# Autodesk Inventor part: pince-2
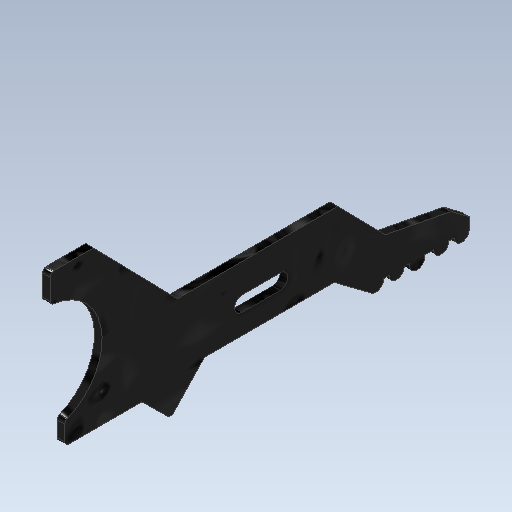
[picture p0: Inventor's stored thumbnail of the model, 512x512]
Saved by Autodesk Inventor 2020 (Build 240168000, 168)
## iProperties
Created: 2021-10
Part Number: pince-2
Material: Générique
Document SubType Name: Modeling
Designer: bruno
Density: 1 g/cm^3
Appearance: Noir
Mass: 0.477223 g
Surface Area: 11.2453 cm^2
Volume: 0.477223 cm^3
Author: bruno
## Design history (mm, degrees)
sketch "Esquisse1"
  geometry: L1 (-4.155, -25.629)-(-4.155, -30.629); L2 (-6.155, -25.629)-(-6.155, -30.629); L3 (7.691, -0.438)-(10.446, -0.438); L4 (-7.207, -2.346)-(-9.233, -2.346); L5 (8.1, -6.586)-(8.1, -6.58); L6 (-11.258, -0.35)-(-11.258, -0.438); L7 (-0.354, -38.146)-(-0.354, -17.123); L8 (-9.733, -12.473)-(-13.092, -15.878); L9 (-6.724, -44.413)-(-8.393, -53.057); L10 (-8.393, -53.057)-(-10.196, -55.455); L11 (-10.196, -55.455)-(-11.607, -55.455); L12 (-12.297, -55.455)-(-12.297, -55.165); L13 (-11.588, -44.203)-(-11.588, -44.904); L14 (-13.08, -16.591)-(-8.776, -20.676); L15 (-8.776, -20.676)-(-8.776, -37.72); L16 (-11.607, -52.755)-(-11.607, -53.455); L17 (-11.596, -46.903)-(-11.596, -47.627); L18 (-11.596, -49.577)-(-11.596, -50.755); L19 (-11.588, -43.757)-(-11.596, -43.741); L20 (-4.7, -24.661)-(-4.7, -29.925); L21 (-0.354, -38.146)-(-0.354, -38.16); L22 (-9.733, -12.473)-(-9.733, -5.167); L23 (10.946, -6.1)-(-0.354, -17.123); L24 (10.946, -4.623)-(10.946, -6.1); L25 (-9.733, -5.167)-(-9.733, -2.846); L26 (-11.607, -54.455)-(-11.207, -54.455); L27 (-0.354, -38.16)-(-6.724, -44.413); L28 (-8.776, -37.72)-(-12.453, -42.615); L29 (-11.588, -14.346)-(-11.596, -14.356); L30 (-13.055, -16.614)-(-13.055, -16.615); L31 (10.946, -4.623)-(10.946, -0.938); C1 r 1.75 at (-5.176, -35.629); C2 r 1.75 at (-5.176, -20.629); A1 r 1 centre (-5.155, -30.629) between (-6.155, -30.629) and (-4.155, -30.629); A2 r 1 centre (-5.155, -25.629) between (-4.155, -25.629) and (-6.155, -25.629); A3 r 7.248 centre (0, 0) between (-6.742, -2.662) and (7.195, -0.878); A4 r 0.5 centre (7.691, -0.938) between (7.691, -0.438) and (7.195, -0.878); A5 r 0.5 centre (-7.207, -2.846) between (-6.742, -2.662) and (-7.207, -2.346); A6 r 1 centre (-11.646, -43.205) between (-12.453, -42.615) and (-11.588, -44.203); A7 r 1 centre (-11.562, -45.904) between (-11.588, -44.904) and (-11.596, -46.903); A8 r 1 centre (-11.818, -48.602) between (-11.596, -47.627) and (-11.596, -49.577); A9 r 1 centre (-11.607, -51.755) between (-11.596, -50.755) and (-11.607, -52.755); A10 r 1 centre (-11.607, -54.455) between (-11.607, -53.455) and (-11.607, -55.455); A11 r 0.5 centre (-12.736, -16.229) between (-13.092, -15.878) and (-13.08, -16.591); A12 r 10.964 centre (0, 0) between (-10.953, -0.495) and (-10.951, -0.523); A13 r 0.5 centre (-10.233, -4.159) between (-9.926, -3.764) and (-9.93, -3.761); A14 r 0.5 centre (-9.233, -2.846) between (-9.233, -2.346) and (-9.733, -2.846); A15 r 10.961 centre (0, 0) between (-10.953, -0.418) and (-10.952, -0.438); A16 r 0.5 centre (10.446, -0.938) between (10.946, -0.938) and (10.446, -0.438); 26 further points
  constraints: 64 end point, 34 point on circle, 18 centre point, 13 point on line, 12 tangent, 9 vertical, 5 coincident, 4 perpendicular, 3 horizontal, 2 parallel, 1 midpoint
  dimensions: "d44" = 2 diameter of A1; "d45" = 2 diameter of A2; "d46" = 5 distance of A1.centre A2.centre; "d67" = 12 distance from line of L4 L29.start; "d81" = 3 distance of L9.end L10.end; "d83" = 2 diameter of A7; "d84" = 2 diameter of A6; "d85" = 2 diameter of A8; "d86" = 2 diameter of A9; "d87" = 2.7 distance of A6.centre A7.centre; "d107" = 0.4 distance of L26.start L26.end; "d108" = 3.5 diameter of C1; "d109" = 3.5 diameter of C2; "d110" = 3.6 distance from line of C1.centre L15; "d111" = 3.6 distance from line of L15 C2.centre; "d112" = 15 distance of C2.centre C1.centre; "d113" = 5 vertical distance of A2.centre C2.centre; "d114" = 0.5 radius of A16
extrude "Extrusion4" new body sketch "Esquisse1" distance "d70" = 1; taper "d71" = 0 deg
node "Solide2"
other parameters: "d5" = 22.5, "d76" = 5, "d78" = 3.5, "d99" = 0.5 (derived), "d100" = 0.5 (derived)
